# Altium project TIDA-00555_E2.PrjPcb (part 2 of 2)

## Sheet Pg8.JTAG Interface + LEDs + Decoupling Capacitors.SchDoc: JTAG Interface + LEDs + Decoupling Capacitors
size 431 x 279 mm; Date: Not shown in title block; ApprovedBy: Not shown in title block; CheckedBy: Not shown in title block; Author: Not shown in title block; CompanyName: Not shown in title block; Engineer: Not shown in title block; Organization: Not shown in title block; Address1: Not shown in title block; Address2: Not shown in title block; Address3: Not shown in title block; Address4: Not shown in title block; DocumentNumber: 5; Revision: Use project parameter SCH_Rev; SheetNumber: 8; SheetTotal: 9; PageSetup: Record=PageOptions¦CenterHorizontal=True¦CenterVertical=True¦PrintScale=1.00¦XCorrection=1.00¦YCorrection=1.00¦PrintKind=0¦BorderSize=5000000¦LeftOffset=0¦BottomOffset=0¦Orientation=2¦PaperLength=1000¦PaperWidth=1000¦Scale=100¦PaperSource=15¦PrintQuality=600¦MediaType=1¦DitherType=10¦PaperKind=Letter¦PrintScaleMode=1
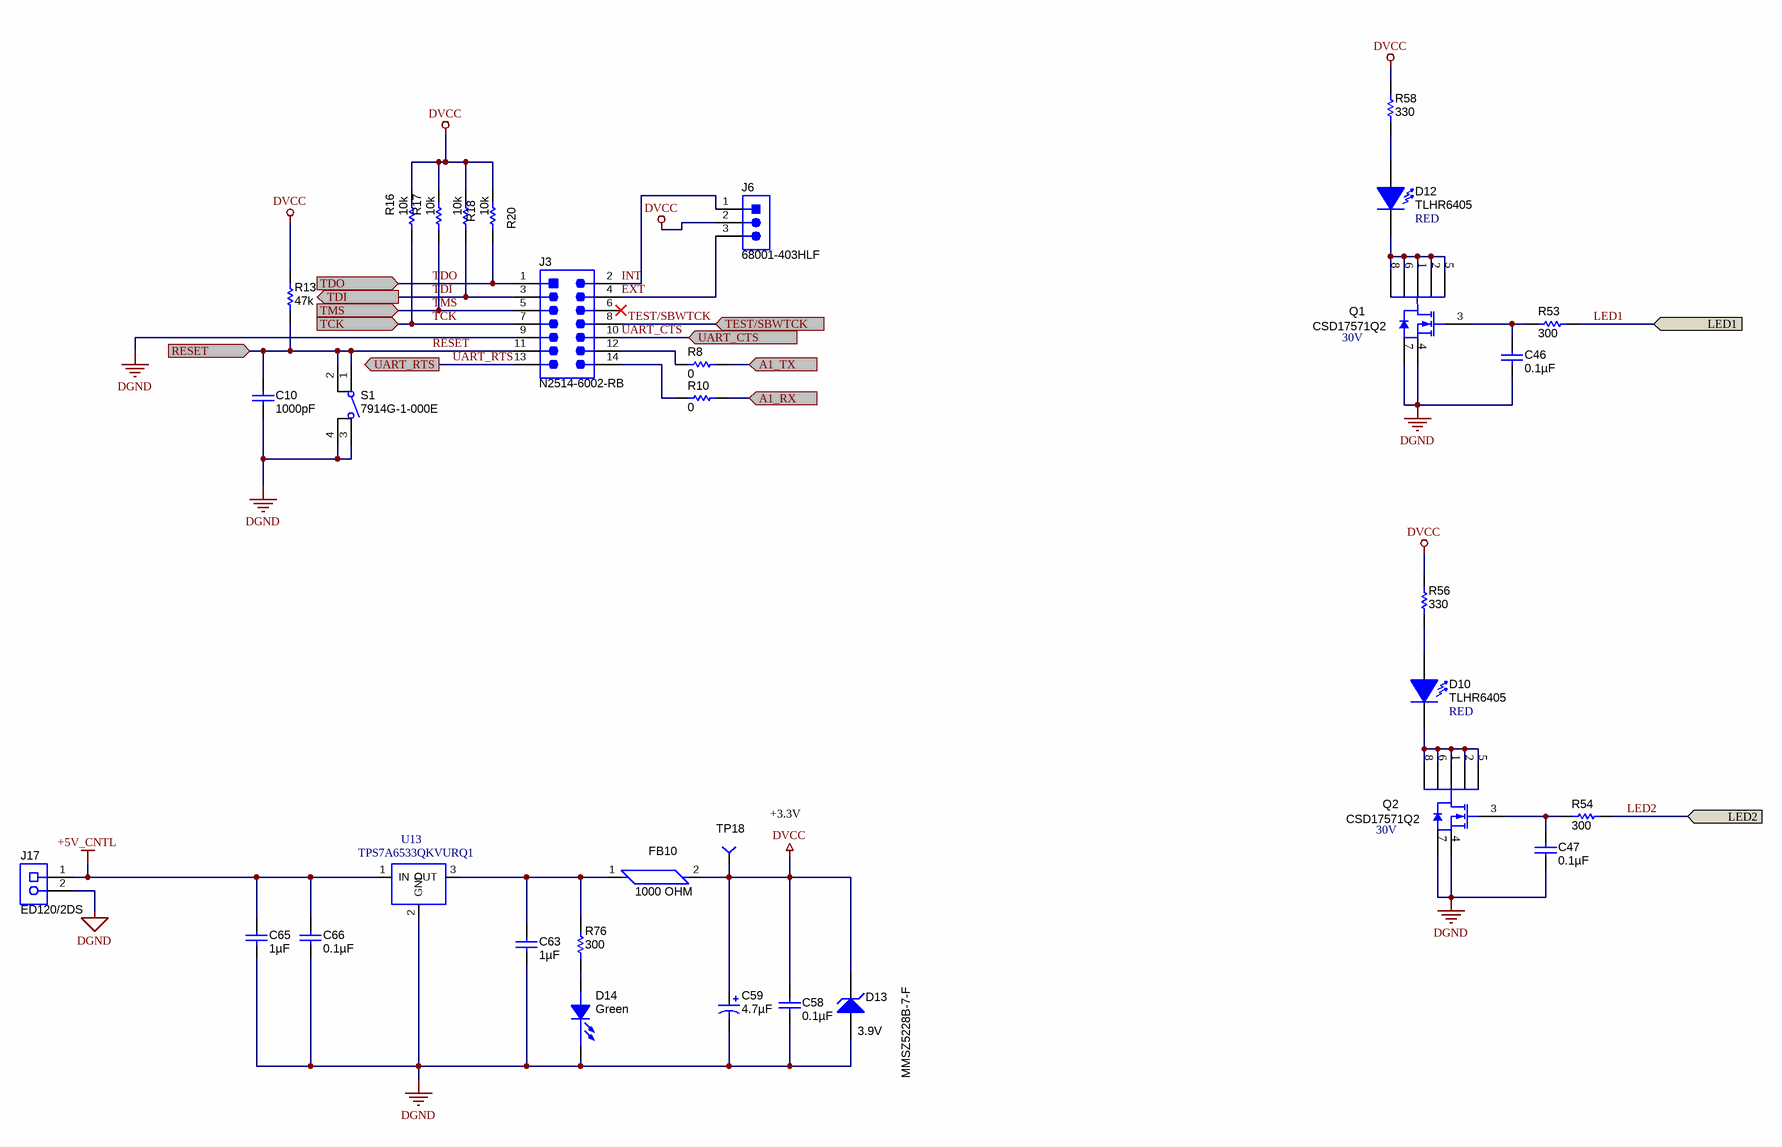
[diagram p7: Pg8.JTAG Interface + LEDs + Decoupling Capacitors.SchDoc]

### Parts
C10  ValueDisplayed: 1000pF  [0603]  (hidden comment: 06035A102KAT2A)
C46  ValueDisplayed: 0.1µF  [0603]  (hidden comment: 06033C104JAT2A)
C47  ValueDisplayed: 0.1µF  [0603]  (hidden comment: 06033C104JAT2A)
C58  ValueDisplayed: 0.1µF  [0603]  (hidden comment: C0603C104K5RACTU)
C59  ValueDisplayed: 4.7µF  [6032-28]  (hidden comment: 293D475X9035C2TE3)
C63  ValueDisplayed: 1µF  [0603]  (hidden comment: GRM188R71C105KA12D)
C65  ValueDisplayed: 1µF  [0603]  (hidden comment: GRM188R71C105KA12D)
C66  ValueDisplayed: 0.1µF  [0603]  (hidden comment: C0603C104K5RACTU)
D10  TLHR6405  value RED  [LED_5MM]
D12  TLHR6405  value RED  [LED_5MM]
D13  MMSZ5228B-7-F  value 3.9V  [sod-123]
D14  value Green  [LED0603AA]  (hidden comment: LED_LG L29K-G2J1-24-Z)
FB10  1000 OHM  [0603]
J3  N2514-6002-RB  [3M_N2514-6002-RB]
J6  68001-403HLF  [HDR1X3]
J17  ED120/2DS  [CONN_ED120-2DS]
Q1  CSD17571Q2  value 30V  [SON_CSD17571Q2]
Q2  CSD17571Q2  value 30V  [SON_CSD17571Q2]
R8  value 0  [0603]  (hidden comment: CRCW06030000Z0EA)
R10  value 0  [0603]  (hidden comment: CRCW06030000Z0EA)
R13  value 47k  [0603]  (hidden comment: CRCW060347K0JNEA)
R16  value 10k  [0603]  (hidden comment: CRCW060310K0JNEA)
R17  value 10k  [0603]  (hidden comment: CRCW060310K0JNEA)
R18  value 10k  [0603]  (hidden comment: CRCW060310K0JNEA)
R20  value 10k  [0603]  (hidden comment: CRCW060310K0JNEA)
R53  value 300  [0603]  (hidden comment: CRCW0603300RJNEA)
R54  value 300  [0603]  (hidden comment: CRCW0603300RJNEA)
R56  value 330  [0603]  (hidden comment: CRCW0603330RJNEA)
R58  value 330  [0603]  (hidden comment: CRCW0603330RJNEA)
R76  value 300  [0603]  (hidden comment: CRCW0603300RJNEA)
S1  7914G-1-000E  [SW_7914G-1-000E]
TP18  TP-040_RND  [TP-040_RND]  (value not drawn)
U13  TPS7A6533QKVURQ1  [KVU_1]

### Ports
A1_RX, A1_TX, LED1 (in), LED2 (in), RESET, TCK, TDI (out), TDO, TEST/SBWTCK, TMS, UART_CTS, UART_RTS

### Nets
+5V_CNTL: C65.1 C66.1 J17.1 U13.1(IN)
DGND: C10.2 C46.2 C47.2 C58.2 C59.2(-) C63.2 C65.2 C66.2 D13.2(A) D14.1(C) J3.9 J17.2 Q1.4(S) Q1.7(S) Q2.4(S) Q2.7(S) S1.3 S1.4 U13.2(GND)
DVCC: C58.1 C59.1(+) D13.1(K) FB10.2 J6.2 R13.2 R16.1 R17.1 R18.1 R20.1 R56.2 R58.2 TP18.1
A1_RX: R10.2 ; port A1_RX
A1_TX: R8.2 ; port A1_TX
EXT: J3.4 J6.3
INT: J3.2 J6.1
LED1: R53.1 ; port LED1
LED2: R54.1 ; port LED2
RESET: C10.1 J3.11 R13.1 S1.1 S1.2 ; port RESET
TCK: J3.7 R16.2 ; port TCK
TDI: J3.3 R18.2 ; port TDI
TDO: J3.1 R20.2 ; port TDO
TEST/SBWTCK: J3.8 ; port TEST/SBWTCK
TMS: J3.5 R17.2 ; port TMS
UART_CTS: J3.10 ; port UART_CTS
UART_RTS: J3.13 ; port UART_RTS
NetC46_1: C46.1 Q1.3(G) R53.2
NetC47_1: C47.1 Q2.3(G) R54.2
NetC63_1: C63.1 FB10.1 R76.2 U13.3(OUT)
NetD10_1: D10.1(K) Q2.1(D) Q2.2(D) Q2.5(D) Q2.6(D) Q2.8(D)
NetD10_2: D10.2(A) R56.1
NetD12_1: D12.1(K) Q1.1(D) Q1.2(D) Q1.5(D) Q1.6(D) Q1.8(D)
NetD12_2: D12.2(A) R58.1
NetD14_2: D14.2(A) R76.1
NetJ3_12: J3.12 R8.1
NetJ3_14: J3.14 R10.1

Not connected (* = marked no-connect by the designer): J3 6*

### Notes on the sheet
- (near TP18) +3.3V

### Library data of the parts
C10 = 06035A102KAT2A: CAP, CERM, 1000 pF, 50 V, +/- 10%, C0G/NP0, 0603; Manufacturer: AVX; Polarized: N; CompType: Capacitor; Value: 1000pF; U/M: EA; Cap_F: 0.000000001; Tolerance_%: 10; ESR_ohm: 0.048; Value1: 0.048 ohm; VDC_V: 50; Value2: 50V; TaMin_C: -55; TaMax_C: 125
C46 C47 = 06033C104JAT2A: CAP, CERM, 0.1uF, 25V, +/-5%, X7R, 0603; Manufacturer: AVX; Polarized: N; CompType: Capacitor; U/M: EA; Cap_F: 0.0000001; Tolerance_%: 5; ESR_Ohm: 0.05; Value1: 0.05 ohm; VDC_V: 25; TaMin_C: -55; TaMax_C: 125
C58 C66 = C0603C104K5RACTU: CAP, CERM, 0.1uF, 50V, +/-10%, X7R, 0603; Manufacturer: Kemet; Polarized: N; CompType: Capacitor; U/M: EA; Cap_F: 0.0000001; Tolerance_%: 10; Value1: Unknown; VDC_V: 50; TaMin_C: -55; TaMax_C: 125
C59 = 293D475X9035C2TE3: CAP, TA, 4.7uF, 35V, +/-10%, 1.9 ohm, SMD; Manufacturer: Vishay-Sprague; Polarized: Y; CompType: Capacitor; U/M: EA; Cap_F: 0.0000047; Tolerance_%: 10; Value1: 1.9 ohm; VDC_V: 35; ESR_Ohm: 1.9; IRMS_A: 0.24; TaMin_C: -55; TaMax_C: 125; Cap_Case: C
C63 C65 = GRM188R71C105KA12D: CAP, CERM, 1 µF, 16 V, +/- 10%, X7R, 0603; Manufacturer: MuRata; Polarized: N; CompType: Capacitor; Value: 1uF; U/M: EA; Cap_F: 0.000001; Tolerance_%: 10; ESR_ohm: 0.011; Value1: 0.011 ohm; VDC_V: 16; Value2: 16V; TaMin_C: -55; TaMax_C: 125
D10 D12 = TLHR6405: LED, 5MM, RED, TH; Manufacturer: VISHAY; SymbolCreator: x0199378
D13 = 1SMB5915BT3G: DIODE ZENER 3.9V 500MW SOD123; Manufacturer: Diodes Incorporated; U/M: EA; Power_W: 0.55; Vz_V: 3.9; Value1: 0.55W; RJA_CperW: 226
D14 = LED_LG L29K-G2J1-24-Z: LED SmartLED Green 570NM; Manufacturer: OSRAM; SymbolCreator: x0120606
FB10 = MMZ1608B102C: FERRITE CHIP 1000 OHM 300MA 0603; Manufacturer: TDK Corporation; CompType: Ferrite Bead
J3 = 0015912140: Header, 7x2, 100mil, SMT; Manufacturer: Molex; SymbolCreator: a0412235; U/M: EA
J6 = 009155003301006: 3 pin berger; Manufacturer: FCI; SymbolCreator: a0799628; CompType: Connector; U/M: EA
J17 = ED120/2DS: TERMINAL BLOCK 5.08MM VERT 2POS, TH; Manufacturer: On-Shore Technology; SymbolCreator: a0412235; U/M: EA
Q1 Q2 = CSD17571Q2: MOSFET, N-CH, 30V, 22A, SON 2X2 MM; Manufacturer: TEXAS INSTRUMENTS; CompType: POWER MOSFET
R8 R10 = CRCW06030000Z0EA: RES, 0 ohm, 5%, 0.1W, 0603; Manufacturer: Vishay-Dale; CompType: Resistor; Value_Code: 0000; Tolerance_%: 5; Power_W: 0.1; VDC_V: 75; TempCo: 200 ppm/C; EIA_Code: E24; U/M: EA
R13 = CRCW060347K0JNEA: RES, 47k ohm, 5%, 0.1W, 0603; Manufacturer: Vishay-Dale; CompType: Resistor; Res_ohm: 47000; Value_Code: 47k0; Tolerance_%: 5; Power_W: 0.1; VDC_V: 75; TempCo: 200 ppm/C; EIA_Code: E24; U/M: EA
R16-R18 R20 = RNCF0603TKY10K0: RES 10K OHM 1/10W 5% 0603 SMD; Manufacturer: Vishay-Dale; CompType: Resistor; Res_ohm: 10000; Value_Code: 10k0; Tolerance_%: 0.01; Value1: 0.01%; Power_W: 0.063; Value2: 0.063W; VDC_V: 50; TempCo: 5 ppm/C; U/M: EA
R53 R54 R76 = CRCW0603300RJNEA: RES, 300 ohm, 5%, 0.1W, 0603; Manufacturer: Vishay-Dale; CompType: Resistor; Value_Code: 300R; Tolerance_%: 5; Power_W: 0.1; VDC_V: 75; TempCo: 200 ppm/C; EIA_Code: E24; U/M: EA
R56 R58 = CRCW0603330RJNEA: RES, 330 ohm, 5%, 0.1W, 0603; Manufacturer: Vishay-Dale; CompType: Resistor; Value_Code: 330R; Tolerance_%: 5; Power_W: 0.1; VDC_V: 75; TempCo: 200 ppm/C; EIA_Code: E24; U/M: EA
S1 = 7914G-1-000E: Switch, Tactile, SPST-NO, 0.1A, 16V, SMT; Manufacturer: Bourns; SymbolCreator: a0412235; VDC_V: 16; SwitchFunction: Off-Mom; PositionCount: 1; CurrentRating_mA: 100
TP18 = TP-040_RND: Test Point, O.040 Hole; Manufacturer: STD; Value: STD
U13 = TPS7A6533QKVURQ1: IC, 300-mA 40-V LOW-DROPOUT REGULATOR WITH 25-uA QUIESCENT CURRENT; Manufacturer: TI; Alternate Manufacturer: None; Area: 136210

## Sheet Pg9-Hardware.SchDoc: Hardware - MIiscellaneous
size 431 x 279 mm; Date: Not shown in title block; ApprovedBy: Not shown in title block; CheckedBy: Not shown in title block; Author: Not shown in title block; CompanyName: Not shown in title block; Engineer: Not shown in title block; Organization: Not shown in title block; Address1: Not shown in title block; Address2: Not shown in title block; Address3: Not shown in title block; Address4: Not shown in title block; DocumentNumber: 7; Revision: Use project parameter SCH_Rev; SheetNumber: 9; SheetTotal: 9; PageSetup: Record=PageOptions|CenterHorizontal=True|CenterVertical=True|PrintScale=0.62|XCorrection=1.00|YCorrection=1.00|PrintKind=0|BorderSize=5000000|LeftOffset=0|BottomOffset=0|Orientation=2|PaperLength=1000|PaperWidth=1000|Scale=100|PaperSource=15|PrintQuality=600|MediaType=1|DitherType=10|PaperKind=Letter|PrintScaleMode=1
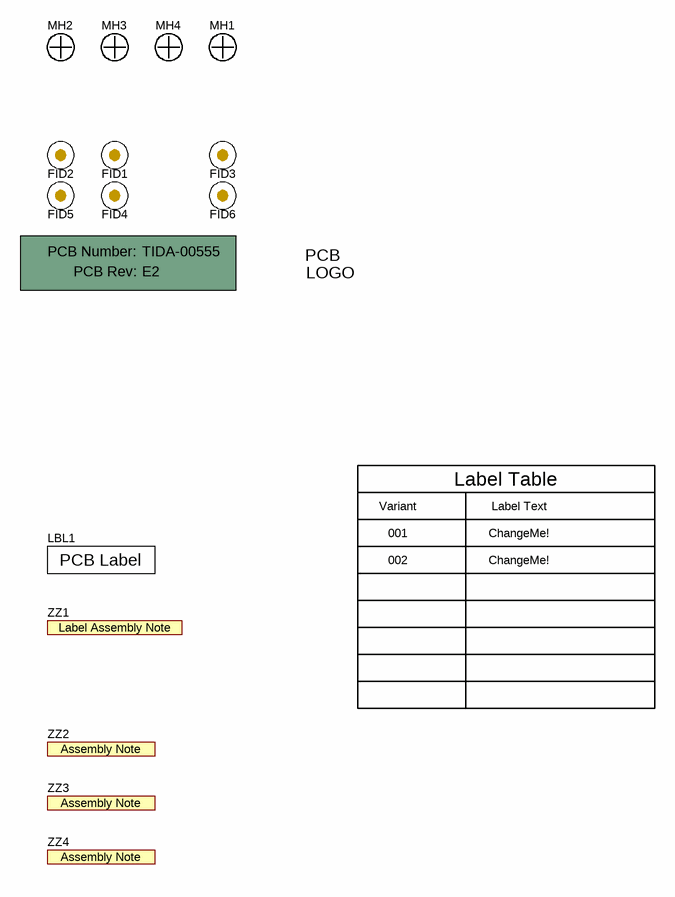
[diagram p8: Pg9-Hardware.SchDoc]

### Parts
!PCB1  (no value)  (mechanical)
FID1  (no value)  [Fiducial10-20]
FID2  (no value)  [Fiducial10-20]
FID3  (no value)  [Fiducial10-20]
FID4  (no value)  [Fiducial10-20]
FID5  (no value)  [Fiducial10-20]
FID6  (no value)  [Fiducial10-20]
LBL1  (no value)  [Label_650x200]
Logo1  (no value)  [TI_Stacked_SolderMask_Small]  (no BOM)
MH1  (no value)  [MH3.2]
MH2  (no value)  [MH3.2]
MH3  (no value)  [MH3.2]
MH4  (no value)  [MH3.2]
ZZ1  (no value)  [AssemblyNoteLabel]  (no BOM)
ZZ2  (no value)  [AssemblyNote]  (no BOM)
ZZ3  (no value)  [AssemblyNote]  (no BOM)
ZZ4  (no value)  [AssemblyNote]  (no BOM)

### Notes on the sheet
- Variant
- Label Table
- Label Text
- 001
- 002
- ChangeMe!

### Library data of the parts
!PCB1 = PCB: Printed Circuit Board; Manufacturer: Any; PartNumber: TIDA-00555; SymbolCreator: a0412235
FID1-FID6 = Fiducial: Fiducial mark.  There is nothing to buy or mount.; SymbolCreator: codlsc
LBL1 = THT-14-423-10: Thermal Transfer Printable Labels, 0.650" W x 0.200" H - 10,000 per roll; Manufacturer: Brady; SymbolCreator: a0412235; CompType: Label; Note: Size: 0.65" x 0.20 "
Logo1 = TI_Logo: Texas Instrument Corporate Signature; SymbolCreator: codlsc
MH1-MH4 = NY PMS 440 0025 PH: Mountin hole, NPTH Drill 3.2mm; CompType: Hardware
ZZ1 = AssemblyNoteLabel: This Assembly Note is for PCB labels only; SymbolCreator: a0412235
ZZ2 = AssemblyNote: These assemblies are ESD sensitive, ESD precautions shall be observed.; SymbolCreator: codlsc
ZZ3 = AssemblyNote: These assemblies must be clean and free from flux and all contaminants. Use of no clean flux is not acceptable.; SymbolCreator: codlsc
ZZ4 = AssemblyNote: These assemblies must comply with workmanship standards IPC-A-610 Class 2, unless otherwise specified.; SymbolCreator: codlsc

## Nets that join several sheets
+5.0V_PH: Pg5-Voltage signal condtioning (18 pins), Pg6-Power supply 1 (5 pins)
+5.0V_USH: Pg4-Current  signal condtioning (6 pins), Pg7-Power supply 2 (5 pins)
+5.0V_VSH: Pg4-Current  signal condtioning (6 pins), Pg7-Power supply 2 (5 pins)
+5.0V_WSH: Pg4-Current  signal condtioning (6 pins), Pg6-Power supply 1 (5 pins)
+5V_CNTL: Pg4-Current  signal condtioning (J28.3), Pg6-Power supply 1 (9 pins), Pg7-Power supply 2 (9 pins), Pg8.JTAG Interface + LEDs + Decoupling Capacitors (C65.1 C66.1 J17.1 U13.1)
-5.0V_PH: Pg5-Voltage signal condtioning (6 pins), Pg6-Power supply 1 (6 pins)
-5.0V_USH: Pg4-Current  signal condtioning (D47.1 D48.1), Pg7-Power supply 2 (6 pins)
-5.0V_VSH: Pg4-Current  signal condtioning (D41.1 D42.1), Pg7-Power supply 2 (6 pins)
-5.0V_WSH: Pg4-Current  signal condtioning (D35.1 D36.1), Pg6-Power supply 1 (6 pins)
AMC_VCC: Pg4-Current  signal condtioning (13 pins), Pg5-Voltage signal condtioning (10 pins)
AVCC: Pg3-Microcontroller (8 pins), Pg4-Current  signal condtioning (J28.1)
DGND: Pg3-Microcontroller (10 pins), Pg4-Current  signal condtioning (11 pins), Pg5-Voltage signal condtioning (9 pins), Pg6-Power supply 1 (11 pins), Pg7-Power supply 2 (11 pins), Pg8.JTAG Interface + LEDs + Decoupling Capacitors (19 pins)
DVCC: Pg3-Microcontroller (10 pins), Pg8.JTAG Interface + LEDs + Decoupling Capacitors (13 pins)
GND_PH: Pg5-Voltage signal condtioning (15 pins), Pg6-Power supply 1 (26 pins)
GND_USH: Pg4-Current  signal condtioning (6 pins), Pg7-Power supply 2 (26 pins)
GND_VSH: Pg4-Current  signal condtioning (6 pins), Pg7-Power supply 2 (26 pins)
GND_WSH: Pg4-Current  signal condtioning (6 pins), Pg6-Power supply 1 (26 pins)
A1_RX: Pg3-Microcontroller (U7.21), Pg8.JTAG Interface + LEDs + Decoupling Capacitors (R10.2)
A1_TX: Pg3-Microcontroller (U7.20), Pg8.JTAG Interface + LEDs + Decoupling Capacitors (R8.2)
DOUTN_CH_U: Pg3-Microcontroller (R32.1), Pg4-Current  signal condtioning (J11.1)
DOUTN_CH_V: Pg3-Microcontroller (R30.1), Pg4-Current  signal condtioning (J19.1)
DOUTN_CH_W: Pg3-Microcontroller (R34.1), Pg4-Current  signal condtioning (J21.1)
DOUTN_U_PH: Pg3-Microcontroller (R41.1), Pg5-Voltage signal condtioning (J23.1)
DOUTN_V_PH: Pg3-Microcontroller (R45.1), Pg5-Voltage signal condtioning (J25.1)
DOUTN_W_PH: Pg3-Microcontroller (R50.1), Pg5-Voltage signal condtioning (J27.1)
DOUTP_CH_U: Pg3-Microcontroller (R31.1), Pg4-Current  signal condtioning (J10.1)
DOUTP_CH_V: Pg3-Microcontroller (R29.1), Pg4-Current  signal condtioning (J18.1)
DOUTP_CH_W: Pg3-Microcontroller (R35.1), Pg4-Current  signal condtioning (J20.1)
DOUTP_U_PH: Pg3-Microcontroller (R42.1), Pg5-Voltage signal condtioning (J22.1)
DOUTP_V_PH: Pg3-Microcontroller (R48.1), Pg5-Voltage signal condtioning (J24.1)
DOUTP_W_PH: Pg3-Microcontroller (R51.1), Pg5-Voltage signal condtioning (J26.1)
LED1: Pg3-Microcontroller (U7.35), Pg8.JTAG Interface + LEDs + Decoupling Capacitors (R53.1)
LED2: Pg3-Microcontroller (U7.34), Pg8.JTAG Interface + LEDs + Decoupling Capacitors (R54.1)
RESET: Pg3-Microcontroller (U7.23), Pg8.JTAG Interface + LEDs + Decoupling Capacitors (5 pins)
TCK: Pg3-Microcontroller (U7.15), Pg8.JTAG Interface + LEDs + Decoupling Capacitors (J3.7 R16.2)
TDI: Pg3-Microcontroller (U7.13), Pg8.JTAG Interface + LEDs + Decoupling Capacitors (J3.3 R18.2)
TDO: Pg3-Microcontroller (U7.12), Pg8.JTAG Interface + LEDs + Decoupling Capacitors (J3.1 R20.2)
TEST/SBWTCK: Pg3-Microcontroller (U7.22), Pg8.JTAG Interface + LEDs + Decoupling Capacitors (J3.8)
TMS: Pg3-Microcontroller (U7.14), Pg8.JTAG Interface + LEDs + Decoupling Capacitors (J3.5 R17.2)
UART_CTS: Pg3-Microcontroller (R28.1), Pg8.JTAG Interface + LEDs + Decoupling Capacitors (J3.10)
UART_RTS: Pg3-Microcontroller (R27.1), Pg8.JTAG Interface + LEDs + Decoupling Capacitors (J3.13)

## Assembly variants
001: not fitted C39 C40 C41 C48 R8 R10 R27 R28 R39 R44 R47 R52 R61 R73 R85 R97 R107 Y1 Y2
